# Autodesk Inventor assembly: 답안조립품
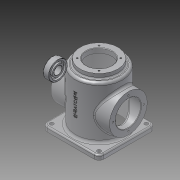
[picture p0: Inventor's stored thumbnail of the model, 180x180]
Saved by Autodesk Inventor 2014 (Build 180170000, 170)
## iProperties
Created: 2015-10
Part Number: 답안조립품
Document SubType Name: Assembly
Designer: Administrator
Author: Administrator
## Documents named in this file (3)
- C:\Users\Administrator\Desktop\451007V1023\답안조립품.iam
- C:\Users\Administrator\Desktop\451007V1023\본체.ipt
- C:\Users\Administrator\Desktop\451007V1023\베어링 6203.ipt
